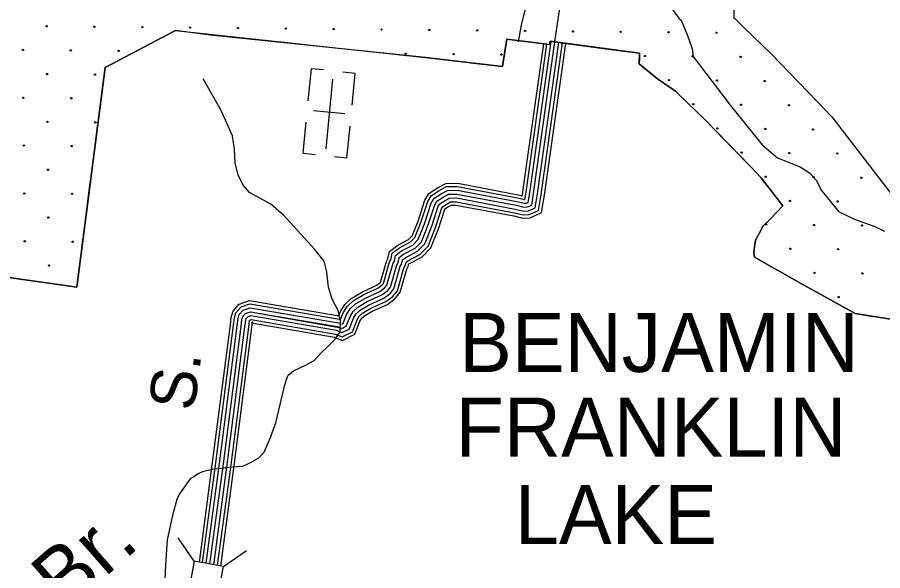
# Model space of a CAD drawing. Extents: x 1788175 to 1969470, y 584502 to 738744.
# Drawn here: x 1820550 to 1827505, y 662427 to 666875 of the extents above; entities that cross this region are included whole.
import ezdxf

# ---------------------------------------------------------------- set-up
doc = ezdxf.new("R2010")
doc.units = 0
for name, color, linetype in [('DESIGN - DRAINAGE - Bridges and Cross Drains Size Text', 7, 'Continuous'), ('DESIGN - EROSION CONTROL - Devices', 7, 'Continuous'), ('DESIGN - ROW - Right-of-Way and Easement Labels', 7, 'Continuous'), ('DESIGN - SCRATCH - User 1', 7, 'Continuous'), ('DESIGN - TRANSPORTATION - Text', 7, 'Continuous'), ('DESIGN - UTILITIES - Cable (Underground) with Text', 7, 'Continuous'), ('SURVEY - DRAINAGE - Area Shapes', 7, 'Continuous'), ('SURVEY - DRAINAGE - Storm Sewer', 7, 'Continuous'), ('SURVEY - TRANSPORTATION - Roads', 7, 'Continuous'), ('SURVEY - VEGETATION - Features with Text', 7, 'Continuous')]:
    doc.layers.add(name, color=color, linetype=linetype)

msp = doc.modelspace()

# ---------------------------------------------------------------- linework, layer by layer
at = {"layer": 'DESIGN - EROSION CONTROL - Devices'}
for centre in [(1820785, 666803.1), (1821169.5, 666799.4), (1821554.1, 666795.6), (1821938.6, 666791.9), (1822323.2, 666788.1), (1822707.7, 666784.4), (1823092.3, 666780.7), (1823476.8, 666776.9), (1823861.4, 666773.2), (1824245.9, 666769.5), (1824630.5, 666765.7), (1825015.1, 666762), (1825399.6, 666758.3), (1825784.2, 666754.5), (1826168.7, 666750.8), (1820594.6, 666612.7), (1820979.1, 666608.9), (1821363.7, 666605.2), (1823671, 666582.8), (1824055.5, 666579.1), (1824440.1, 666575.3), (1825593.8, 666564.1), (1825978.3, 666560.4), (1826362.9, 666556.7), (1820788.7, 666418.5), (1821173.3, 666414.8), (1825787.9, 666370), (1826172.4, 666366.3), (1826557, 666362.5), (1820598.3, 666228.1), (1820982.8, 666224.4), (1825982, 666175.9), (1826366.6, 666172.1), (1826751.1, 666168.4), (1820792.4, 666034), (1821177, 666030.2), (1826176.2, 665981.7), (1826560.7, 665978), (1826945.3, 665974.2), (1820602, 665843.6), (1820986.6, 665839.8), (1826370.3, 665787.6), (1826754.9, 665783.8), (1827139.4, 665780.1), (1820796.2, 665649.4), (1826564.5, 665593.4), (1826949, 665589.7), (1827333.6, 665586), (1820605.8, 665459), (1820990.3, 665455.3), (1826758.6, 665399.3), (1827143.2, 665395.5), (1820799.9, 665264.9), (1826568.2, 665208.9), (1826952.8, 665205.1), (1827337.3, 665201.4), (1820609.5, 665074.5), (1820994, 665070.7), (1826762.3, 665014.7), (1827146.9, 665011), (1820803.6, 664880.3), (1826956.5, 664820.6), (1827341, 664816.8), (1827150.6, 664626.4)]:
    msp.add_circle(centre, 5.28, dxfattribs=at)
at = {"layer": 'DESIGN - SCRATCH - User 1'}
for points in [[(1821012.6, 667171.2), (1821691.3, 667538), (1823819.3, 667307), (1823855, 667533.8), (1824264.1, 667482.5), (1824271.8, 667512.6), (1826317.2, 667242.4), (1826307.9, 666868.5), (1826317.6, 666861.7), (1826386.4, 666795.3), (1826607, 666580.8), (1826981.8, 666194.8), (1827097, 666073.9), (1827688.9, 665306.5), (1828612.1, 665043.1)], [(1828495, 664302.3), (1827284.2, 664493.7), (1826856.9, 664730.8), (1826474.1, 664946.8), (1826468, 664983), (1826473.2, 665028.9), (1826481.5, 665082.7), (1826510.9, 665138), (1826544.4, 665199.3), (1826597.7, 665250.1), (1826701.5, 665358.7), (1826527, 665584.9), (1826441.3, 665674.9), (1826076.5, 666050.6), (1825864.5, 666256.6), (1825840.1, 666280.2), (1825695.5, 666380.7), (1825548.4, 666500.1), (1825550.6, 666587.1), (1824832.6, 666682), (1824826, 666656.1), (1824482.9, 666699.2), (1824448.4, 666479.9), (1823830.9, 666551.3), (1822100.9, 666731.9), (1821821.4, 666769.4), (1821255.6, 666470.4), (1821027.6, 664705.1), (1819650.8, 664901.4)]]:
    msp.add_lwpolyline(points, dxfattribs=at)
at = {"layer": 'DESIGN - TRANSPORTATION - Text'}
for points in [[(1825231.6, 667699.4), (1825269.1, 667632), (1825320.2, 667566), (1825369.1, 667487.2), (1825396.3, 667394.3), (1825445.7, 667351.7), (1825488.5, 667261.1), (1825505.6, 667190.8), (1825562.7, 667120), (1825632.1, 667083.2), (1825693.8, 667058.4), (1825753, 667005.6), (1825798.5, 666963), (1825835.7, 666908.5), (1825867.2, 666868.1), (1825884.7, 666853)], [(1824683.2, 667094.7), (1824656.5, 667043.9), (1824633.8, 666951.5), (1824598.2, 666813.8), (1824575.1, 666679.1)], [(1825884.7, 666853), (1825936.1, 666729.7), (1825973.4, 666622.7), (1825981.4, 666558.9), (1826279.2, 666167.6), (1826536.8, 665851.3), (1826658, 665744.9), (1826765.3, 665702.2), (1826842.1, 665674.5), (1826915.6, 665624.8), (1826969.3, 665566.4), (1827013.8, 665483), (1827081.1, 665397.7), (1827148.9, 665314), (1827278.1, 665253.1)], [(1822588.9, 663513), (1822627.9, 663616.5), (1822697.1, 663909.5), (1822714, 663963.3), (1822726.7, 663999.1), (1822769.2, 664032.4), (1822872, 664082.6), (1822936.5, 664117.5), (1822989.5, 664174.6), (1823050.5, 664235.6), (1823101.3, 664284.7), (1823144.4, 664348), (1823148, 664438.1), (1823127.5, 664518.5), (1823081.1, 664609.4), (1823050.9, 664706), (1823037.1, 664826.4), (1823014.7, 664914.9), (1822938.5, 665012.3), (1822687.7, 665285), (1822587.4, 665372.9), (1822494.4, 665424.5), (1822415.3, 665468), (1822366.3, 665522.9), (1822323.8, 665605.7), (1822299.6, 665704.3), (1822295.6, 665814.4), (1822279.5, 665922.8), (1822187.3, 666126.6), (1822042, 666381.5)], [(1827278.1, 665253.1), (1827359.1, 665222.5), (1827440.6, 665193.5), (1827520.1, 665156.5)], [(1822588.9, 663513), (1822529.7, 663376.5), (1822488.6, 663331.3), (1822431.1, 663298.5), (1822390, 663277.9), (1822357.1, 663265.6), (1822316.1, 663261.5), (1822246.2, 663257.4), (1822225.7, 663253.3), (1822188.7, 663249.2), (1822114.8, 663241), (1822036.7, 663220.4), (1822007.9, 663208.1), (1821962.8, 663179.4), (1821942.2, 663167), (1821913.5, 663134.2), (1821892.9, 663101.3), (1821851.8, 663043.8), (1821831.3, 662998.6), (1821802.5, 662891.8), (1821786.1, 662821.9), (1821753.2, 662674.1), (1821740.9, 662472.8), (1821731.9, 662290.4)]]:
    msp.add_lwpolyline(points, dxfattribs=at)
at = {"layer": 'DESIGN - UTILITIES - Cable (Underground) with Text'}
for p, q in [((1822910.3, 666462), (1822885.3, 666202.4)), ((1823009.4, 666452.5), (1822910.8, 666462)), ((1823264.6, 666424), (1823165.3, 666433.5)), ((1823239.9, 666168.4), (1823264.5, 666424)), ((1823183, 666099.1), (1822930.5, 666123.4)), ((1822868.9, 666032.3), (1822844.8, 665781.9)), ((1823199.1, 665743.9), (1823223.8, 666000.8)), ((1822845, 665781.9), (1822942.8, 665772.5)), ((1823198.9, 665743.9), (1823099.8, 665753.4))]:
    msp.add_line(p, q, dxfattribs=at)
msp.add_lwpolyline([(1823083.9, 666377.6), (1823030, 665817.2)], dxfattribs=at)
at = {"layer": 'SURVEY - DRAINAGE - Area Shapes'}
msp.add_lwpolyline([(1824870.7, 666676.9), (1824927.2, 667078.2)], dxfattribs=at)
at = {"layer": 'SURVEY - DRAINAGE - Storm Sewer'}
for p, q in [((1821971.9, 662504.1), (1821843.6, 662691.5)), ((1822205.4, 662460.3), (1822392.8, 662588.5))]:
    msp.add_line(p, q, dxfattribs=at)
msp.add_lwpolyline([(1822161.6, 662226.8), (1822205.4, 662460.3), (1821971.9, 662504.1), (1821928.1, 662270.6)], close=True, dxfattribs=at)
at = {"layer": 'SURVEY - TRANSPORTATION - Roads'}
for points in [[(1823115.6, 664297.2), (1823162.8, 664278), (1823262.5, 664328.7), (1823303.1, 664431.8), (1823317.8, 664455.5), (1823339, 664476), (1823402.3, 664513), (1823523.7, 664567.2), (1823584.4, 664612.7), (1823627.3, 664664.6), (1823680.3, 664851.2), (1823692, 664871.5), (1823696.6, 664892.8), (1823701.3, 664896.3), (1823799.6, 664947.8), (1823872.5, 665021.3), (1823934.5, 665175.9), (1823985.1, 665332.7), (1823986.2, 665334.6), (1824016.1, 665354.3), (1824038.1, 665365.8), (1824074.2, 665366.3), (1824539.6, 665278.3), (1824613.7, 665260.7), (1824670.7, 665263.9), (1824762.7, 665305.4), (1824786, 665446.6), (1824957.7, 666665.5)], [(1823125.4, 664321), (1823161.6, 664306.2), (1823242.2, 664347.2), (1823280, 664443.4), (1823297.6, 664471.8), (1823323.3, 664496.7), (1823390.6, 664536), (1823510.6, 664589.5), (1823566.5, 664631.4), (1823604, 664676.8), (1823656.4, 664861.3), (1823667.7, 664880.8), (1823673.5, 664907.6), (1823687.5, 664918.2), (1823784.2, 664968.8), (1823850.6, 665035.7), (1823910.3, 665184.6), (1823961.5, 665343.4), (1823967.1, 665352.8), (1824003.1, 665376.5), (1824031.6, 665391.4), (1824076.5, 665392), (1824545, 665303.4), (1824616, 665286.6), (1824664.5, 665289.3), (1824739.5, 665323.1), (1824760.6, 665450.5), (1824932.2, 666668.8)], [(1823133.9, 664478.2), (1823146.5, 664510.4), (1823181, 664565.8), (1823232.7, 664616), (1823322.6, 664668.5), (1823434.8, 664718.6), (1823463.2, 664739.8), (1823469.5, 664747.4), (1823518.4, 664919.6), (1823527.3, 664935), (1823539.9, 664993.2), (1823607.8, 665044.3), (1823694.8, 665089.9), (1823723.8, 665119), (1823770.3, 665235.2), (1823825.1, 665404.8), (1823856.7, 665458.2), (1823927.5, 665504.7), (1823994, 665539.7), (1824089.4, 665541), (1824575.9, 665448.9), (1824608.4, 665441.3), (1824613.6, 665473), (1824781, 666661.8)], [(1823137.1, 664349.7), (1823160.2, 664340.3), (1823217.6, 664369.5), (1823252.2, 664457.4), (1823273.3, 664491.4), (1823304.4, 664521.6), (1823376.4, 664563.6), (1823494.8, 664616.4), (1823545, 664654), (1823576, 664691.5), (1823627.6, 664873.4), (1823638.4, 664892.1), (1823645.7, 664925.5), (1823670.9, 664944.4), (1823765.6, 664994), (1823824.2, 665053.1), (1823881.1, 665195.2), (1823933, 665356.2), (1823944.1, 665374.8), (1823987.3, 665403.2), (1824023.7, 665422.3), (1824079.2, 665423.1), (1824551.4, 665333.8), (1824618.8, 665317.8), (1824657, 665319.9), (1824711.7, 665344.6), (1824730, 665455.2), (1824901.4, 666672.9)], [(1823147.7, 664445.9), (1823168.7, 664499.3), (1823200.4, 664550.2), (1823247.8, 664596.2), (1823333.9, 664646.4), (1823447.4, 664697.1), (1823480.4, 664721.8), (1823491.8, 664735.7), (1823541.3, 664909.9), (1823550.6, 664926), (1823562.1, 664979), (1823621, 665023.3), (1823709.7, 665069.7), (1823744.9, 665105.2), (1823793.6, 665226.8), (1823847.7, 665394.6), (1823875, 665440.7), (1823940, 665483.4), (1824000.2, 665515), (1824087.2, 665516.2), (1824570.8, 665424.8), (1824627.1, 665411.4), (1824628.5, 665411.5), (1824638, 665469.2), (1824805.5, 666658.7)], [(1823148.8, 664378.4), (1823158.8, 664374.4), (1823193.1, 664391.8), (1823224.4, 664471.4), (1823249, 664511), (1823285.5, 664546.4), (1823362.2, 664591.2), (1823479, 664643.3), (1823523.5, 664676.6), (1823547.9, 664706.2), (1823598.9, 664885.6), (1823609.2, 664903.4), (1823617.8, 664943.3), (1823654.2, 664970.7), (1823746.9, 665019.2), (1823797.8, 665070.5), (1823851.9, 665205.7), (1823904.6, 665369), (1823921, 665396.7), (1823971.5, 665429.9), (1824015.9, 665453.2), (1824081.8, 665454.1), (1824557.9, 665364.1), (1824621.6, 665349), (1824649.6, 665350.6), (1824683.8, 665366), (1824699.3, 665459.8), (1824870.7, 666676.9)], [(1823148.8, 664378.4), (1823158.8, 664374.4), (1823193.1, 664391.8), (1823224.4, 664471.4), (1823249, 664511), (1823285.5, 664546.4), (1823362.2, 664591.2), (1823479, 664643.3), (1823523.5, 664676.6), (1823547.9, 664706.2), (1823598.9, 664885.6), (1823609.2, 664903.4), (1823617.8, 664943.3), (1823654.2, 664970.7), (1823746.9, 665019.2), (1823797.8, 665070.5), (1823851.9, 665205.7), (1823904.6, 665369), (1823921, 665396.7), (1823971.5, 665429.9), (1824015.9, 665453.2), (1824081.8, 665454.1), (1824557.9, 665364.1), (1824621.6, 665349), (1824649.6, 665350.6), (1824683.8, 665366), (1824699.3, 665459.8), (1824870.7, 666676.9)], [(1823157.4, 664408.4), (1823168.5, 664414.1), (1823196.5, 664485.3), (1823224.7, 664530.6), (1823266.7, 664571.3), (1823348, 664618.8), (1823463.2, 664670.2), (1823501.9, 664699.2), (1823519.9, 664721), (1823570.1, 664897.7), (1823579.9, 664914.7), (1823590, 664961.2), (1823637.6, 664997), (1823728.3, 665044.5), (1823771.3, 665087.8), (1823822.8, 665216.2), (1823876.2, 665381.8), (1823898, 665418.7), (1823955.8, 665456.7), (1824008.1, 665484.1), (1824084.5, 665485.2), (1824564.3, 665394.4), (1824624.3, 665380.2), (1824642.1, 665381.2), (1824655.9, 665387.4), (1824668.7, 665464.5), (1824840, 666681)], [(1822012.8, 662496.4), (1822119.6, 663296.4), (1822261.9, 664402.7), (1822269.6, 664465.4), (1822283.2, 664512.3), (1822333.8, 664570.3), (1822417, 664597.9), (1823136.5, 664474.6)], [(1822037.2, 662491.9), (1822144.2, 663293.2), (1822286.4, 664399.7), (1822293.9, 664460.4), (1822305.4, 664500.2), (1822348, 664548.9), (1822418.9, 664572.5), (1823140.3, 664448.9), (1823145.7, 664446.7)], [(1822067.7, 662486.1), (1822174.9, 663289.1), (1822317.1, 664395.8), (1822324.4, 664454.1), (1822333.3, 664485), (1822365.8, 664522.2), (1822421.3, 664540.6), (1823131.7, 664419), (1823146.7, 664412.8)], [(1822098.2, 662480.4), (1822205.6, 663285.1), (1822347.9, 664391.9), (1822354.8, 664447.8), (1822361.2, 664469.8), (1822383.6, 664495.4), (1822423.8, 664508.8), (1823123.1, 664389), (1823148.8, 664378.4)], [(1822098.2, 662480.4), (1822205.6, 663285.1), (1822347.9, 664391.9), (1822354.8, 664447.8), (1822361.2, 664469.8), (1822383.6, 664495.4), (1822423.8, 664508.8), (1823148.8, 664378.4)], [(1822128.7, 662474.7), (1822236.4, 663281.1), (1822378.6, 664388), (1822385.3, 664441.6), (1822389, 664454.5), (1822401.4, 664468.7), (1822426.2, 664476.9), (1823114.5, 664359), (1823137.1, 664349.7)], [(1822159.2, 662469), (1822267.1, 663277), (1822409.4, 664384.1), (1822415.7, 664435.3), (1822416.9, 664439.3), (1822419.2, 664441.9), (1822428.6, 664445), (1823105.9, 664329), (1823125.4, 664321.1)], [(1822184.5, 662464.2), (1822292.6, 663273.7), (1822434.9, 664380.9), (1822441, 664430.1), (1822440, 664426.7), (1822433.9, 664419.7), (1822430.6, 664418.6), (1823098.8, 664304.1), (1823115.6, 664297.2)]]:
    msp.add_lwpolyline(points, dxfattribs=at)
at = {"layer": 'SURVEY - VEGETATION - Features with Text'}
for points in [[(1819650.8, 664901.4), (1821027.6, 664705.1), (1821255.6, 666470.4), (1821821.4, 666769.4), (1823830.9, 666551.3), (1824448.4, 666479.9), (1824482.9, 666699.2), (1824826, 666656.1), (1824832.6, 666682), (1825550.6, 666587.1), (1825548.4, 666500.1), (1825695.5, 666380.7), (1825840.1, 666280.2), (1825864.5, 666256.6), (1826076.5, 666050.6), (1826441.3, 665674.9), (1826527, 665584.9), (1826701.5, 665358.7), (1826597.7, 665250.1), (1826544.4, 665199.3), (1826510.9, 665138), (1826481.5, 665082.7), (1826473.2, 665028.9), (1826468, 664983), (1826474.1, 664946.8), (1826856.9, 664730.8), (1827284.2, 664493.7), (1828495, 664302.3)], [(1821763.9, 666739.1), (1821821.4, 666769.4), (1822019.2, 666748)], [(1822019.2, 666748), (1822281.7, 666719.5)], [(1822430.8, 666703.3), (1822693.3, 666674.8)], [(1824449, 666483.9), (1824482.9, 666699.2), (1824528.6, 666693.4)], [(1821397.9, 666545.6), (1821631.3, 666669)], [(1822693.3, 666674.8), (1822955.7, 666646.3)], [(1823104.8, 666630.2), (1823367.3, 666601.7)], [(1824528.6, 666693.4), (1824790.5, 666660.6)], [(1824919.4, 666670.5), (1825181.2, 666635.9)], [(1825181.2, 666635.9), (1825442.9, 666601.4)], [(1823367.3, 666601.7), (1823629.8, 666573.2)], [(1821242.4, 666368.2), (1821255.6, 666470.4), (1821397.9, 666545.6)], [(1823778.9, 666557), (1823830.9, 666551.3), (1824041.2, 666527)], [(1824041.2, 666527), (1824303.4, 666496.7)], [(1825549.6, 666545.8), (1825548.4, 666500.1), (1825695.5, 666380.7), (1825719.2, 666364.2)], [(1825719.2, 666364.2), (1825840.1, 666280.2), (1825864.5, 666256.6), (1825923.9, 666198.9)], [(1821189.3, 665957.6), (1821223.1, 666219.4)], [(1826031.5, 666094.3), (1826076.5, 666050.6), (1826216.7, 665906.2)], [(1821155.5, 665695.8), (1821189.3, 665957.6)], [(1826216.7, 665906.2), (1826400.6, 665716.8)], [(1826504.4, 665608.6), (1826527, 665584.9), (1826668.3, 665401.8)], [(1821102.5, 665285.2), (1821136.3, 665547)], [(1826668.3, 665401.8), (1826701.5, 665358.7), (1826597.7, 665250.1), (1826554.7, 665209.1)], [(1821068.7, 665023.4), (1821102.5, 665285.2)], [(1826481, 665079.5), (1826473.2, 665028.9), (1826468, 664983), (1826474.1, 664946.8), (1826587.3, 664882.9)], [(1820935.4, 664718.3), (1821027.6, 664705.1), (1821049.5, 664874.6)], [(1826587.3, 664882.9), (1826817.2, 664753.2)], [(1820674.1, 664755.5), (1820935.4, 664718.3)], [(1826948.2, 664680.1), (1827179, 664552)], [(1827179, 664552), (1827284.2, 664493.7), (1827426.2, 664471.2)]]:
    msp.add_lwpolyline(points, dxfattribs=at)

# ---------------------------------------------------------------- texts
at = {"layer": 'DESIGN - DRAINAGE - Bridges and Cross Drains Size Text'}
for s, p in [('BENJAMIN', (1824100.6, 664023.7)), ('FRANKLIN', (1824072.4, 663342.7)), ('LAKE', (1824549, 662640.8))]:
    msp.add_text(s, height=475, dxfattribs=at).set_placement(p)
msp.add_text('Br.', height=475, rotation=41.18953, dxfattribs=at).set_placement((1820933.5, 662090.9))
at = {"layer": 'DESIGN - ROW - Right-of-Way and Easement Labels'}
msp.add_text('S.', height=370, rotation=82.67557, dxfattribs=at).set_placement((1821971, 663703))

doc.saveas('drawing.dxf')
